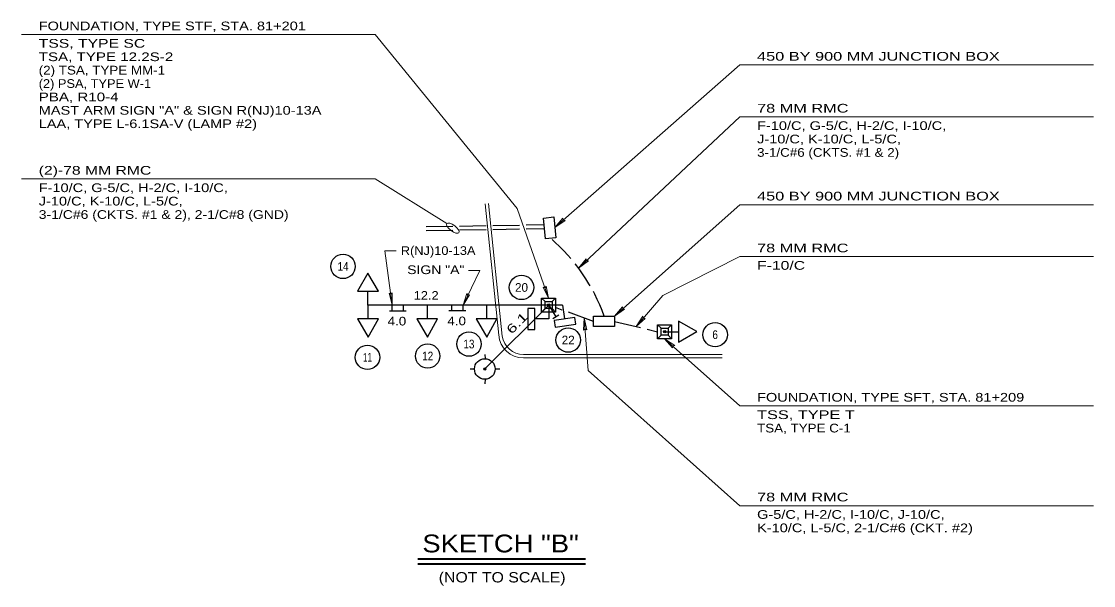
# Model space of a CAD drawing. Extents: x 168203 to 169863, y 223196 to 223870.
# Drawn here: x 168659.4 to 168731.8, y 223261.7 to 223299.8 of the extents above; entities that cross this region are included whole.
import ezdxf
from ezdxf.enums import TextEntityAlignment as Align

# ---------------------------------------------------------------- set-up
doc = ezdxf.new("R2010")
doc.units = 0
doc.header["$LTSCALE"] = 0.3
doc.header["$PDMODE"] = 32
doc.header["$PDSIZE"] = 0.15
doc.linetypes.add('LONG_DASH_SHORT_DASH', pattern=[9.9, 6, -1.2, 1.5, -1.2])
doc.linetypes.add('LONG_DASHED', pattern=[7.5, 6, -1.5])
for name, color, linetype, lineweight in [('1', 7, 'Continuous', 13), ('3', 7, 'Continuous', 25), ('31', 7, 'Continuous', 25), ('5', 7, 'Continuous', 25), ('6', 7, 'LONG_DASHED', 25), ('7', 7, 'Continuous', 25), ('9', 7, 'Continuous', 13)]:
    doc.layers.add(name, color=color, linetype=linetype, lineweight=lineweight)

msp = doc.modelspace()

# ---------------------------------------------------------------- linework, layer by layer
at = {"layer": '1'}
for p, q in [((168691.6329, 223278.6176), (168690.7124, 223287.4748)), ((168691.8712, 223278.5504), (168690.9412, 223287.4985)), ((168706.7124, 223277.0758), (168693.2955, 223277.0758)), ((168706.7124, 223277.3058), (168693.3035, 223277.3058))]:
    msp.add_line(p, q, dxfattribs=at)
for radius, start, end in [(1.6673, 184.13349, 270.00005), (1.4373, 187.706, 270.3211)]:
    msp.add_arc((168693.2955, 223278.7431), radius, start, end, dxfattribs=at)
at = {"layer": '3'}
for p, q in [((168694.5256, 223281.113), (168694.7605, 223280.878)), ((168695.4653, 223281.113), (168695.2304, 223280.878)), ((168694.5256, 223280.1732), (168694.7605, 223280.4082)), ((168695.4653, 223280.1732), (168695.2304, 223280.4082)), ((168702.3536, 223279.313), (168702.5885, 223279.078)), ((168703.2933, 223279.313), (168703.0584, 223279.078)), ((168702.3536, 223278.3732), (168702.5885, 223278.6082)), ((168703.2933, 223278.3732), (168703.0584, 223278.6082))]:
    msp.add_line(p, q, dxfattribs=at)
for points in [[(168694.5256, 223281.113), (168695.4653, 223281.113), (168695.4653, 223280.1732), (168694.5256, 223280.1732)], [(168694.7605, 223280.878), (168695.2304, 223280.878), (168695.2304, 223280.4082), (168694.7605, 223280.4082)], [(168702.3536, 223279.313), (168703.2933, 223279.313), (168703.2933, 223278.3732), (168702.3536, 223278.3732)], [(168702.5885, 223279.078), (168703.0584, 223279.078), (168703.0584, 223278.6082), (168702.5885, 223278.6082)]]:
    msp.add_lwpolyline(points, close=True, dxfattribs=at)
for p in [(168695.0045, 223280.6431), (168702.8325, 223278.8431)]:
    msp.add_point(p, dxfattribs=at)
at = {"layer": '31', "lineweight": 13}
for p, q in [((168683.9455, 223284.304), (168684.7042, 223284.304)), ((168684.4429, 223280.643), (168683.9455, 223284.304)), ((168689.2219, 223280.6438), (168690.3583, 223282.9722)), ((168689.5996, 223282.9722), (168690.3583, 223282.9722))]:
    msp.add_line(p, q, dxfattribs=at)
at = {"layer": '31'}
for p, q in [((168682.8045, 223280.6431), (168682.8045, 223281.5829)), ((168695.0045, 223280.6431), (168682.8045, 223280.6431)), ((168682.8045, 223280.6431), (168682.8045, 223279.7033)), ((168684.4429, 223280.2635), (168684.4429, 223280.643)), ((168685.2019, 223280.2635), (168685.2019, 223280.643)), ((168686.8045, 223280.6431), (168686.8045, 223279.7033)), ((168688.4629, 223280.2643), (168688.4629, 223280.6438)), ((168689.2219, 223280.2643), (168689.2219, 223280.6438)), ((168695.0045, 223280.6431), (168690.6912, 223276.3297)), ((168690.8045, 223280.6431), (168690.8045, 223279.7033)), ((168695.0045, 223280.6431), (168695.0045, 223279.7033)), ((168695.9443, 223280.6431), (168695.0045, 223280.6431)), ((168695.0045, 223280.6431), (168695.4929, 223279.8402)), ((168695.9443, 223280.6431), (168696.0776, 223279.7128)), ((168684.2531, 223280.2635), (168685.3826, 223280.2635)), ((168688.2731, 223280.2643), (168689.4026, 223280.2643)), ((168695.0045, 223279.7033), (168694.0647, 223279.7033)), ((168695.6936, 223279.9623), (168695.2844, 223279.7134)), ((168702.8325, 223278.8431), (168703.7723, 223278.8431))]:
    msp.add_line(p, q, dxfattribs=at)
at = {"layer": '31', "linetype": 'LONG_DASH_SHORT_DASH'}
for points in [[(168682.7864, 223282.8027), (168682.0997, 223281.5829), (168682.8045, 223281.5829), (168683.5093, 223281.5829)], [(168693.5949, 223280.4172), (168693.5949, 223278.9985), (168694.0647, 223278.9985), (168694.0647, 223280.4172)], [(168682.8226, 223278.4835), (168683.5093, 223279.7033), (168682.8045, 223279.7033), (168682.0997, 223279.7033)], [(168686.8226, 223278.4835), (168687.5093, 223279.7033), (168686.8045, 223279.7033), (168686.0997, 223279.7033)], [(168690.8226, 223278.4835), (168691.5093, 223279.7033), (168690.8045, 223279.7033), (168690.0997, 223279.7033)], [(168704.9921, 223278.8612), (168703.7723, 223279.5479), (168703.7723, 223278.8431), (168703.7723, 223278.1383)]]:
    msp.add_lwpolyline(points, close=True, dxfattribs=at)
at = {"layer": '31', "lineweight": 13}
for points in [[(168684.4319, 223281.4623), (168684.4429, 223280.643), (168684.226, 223281.4343), (168684.3444, 223281.3682)], [(168689.6679, 223281.3311), (168689.2219, 223280.6438), (168689.4812, 223281.4222), (168689.5429, 223281.3015)]]:
    msp.add_lwpolyline(points, close=True, dxfattribs=at)
at = {"layer": '31'}
msp.add_lwpolyline([(168695.4376, 223279.1465), (168696.8419, 223279.3477), (168696.7753, 223279.8128), (168695.3709, 223279.6115)], close=True, dxfattribs=at)
for centre in [(168681.124, 223283.2489), (168693.1689, 223281.8297), (168696.3185, 223278.2827), (168706.2354, 223278.644), (168689.6214, 223278.0132), (168682.7725, 223277.116), (168686.8368, 223277.2049)]:
    msp.add_circle(centre, 0.8236, dxfattribs=at)
at = {"layer": '5'}
for points in [[(168694.7902, 223285.1007), (168694.6436, 223286.5118), (168695.3446, 223286.5846), (168695.4912, 223285.1735)], [(168699.4522, 223279.1952), (168698.0335, 223279.1952), (168698.0335, 223279.9), (168699.4522, 223279.9)]]:
    msp.add_lwpolyline(points, close=True, dxfattribs=at)
at = {"layer": '6'}
for p, q in [((168686.7262, 223285.9341), (168694.6895, 223286.0701)), ((168686.7307, 223285.6699), (168694.7169, 223285.8063)), ((168698.0335, 223279.5431), (168695.4653, 223280.4672)), ((168699.4522, 223279.5431), (168702.3536, 223278.8431))]:
    msp.add_line(p, q, dxfattribs=at)
msp.add_arc((168687.1701, 223275.8053), 12.2757, 19.48491, 49.48362, dxfattribs=at)
at = {"layer": '7'}
for p, q in [((168690.7007, 223277.3169), (168690.7071, 223277.0294)), ((168689.9915, 223276.3265), (168689.704, 223276.3201)), ((168691.704, 223276.3265), (168691.3845, 223276.3265)), ((168690.7072, 223275.6365), (168690.7008, 223275.3233))]:
    msp.add_line(p, q, dxfattribs=at)
msp.add_circle((168690.6912, 223276.3297), 0.6965, dxfattribs=at)
msp.add_point((168690.6944, 223276.3265), dxfattribs=at)
at = {"layer": '9'}
for p, q in [((168683.2943, 223298.8853), (168659.4208, 223298.8853)), ((168695.4269, 223285.88), (168707.8988, 223296.8353)), ((168731.7723, 223296.8353), (168707.8988, 223296.8353)), ((168697.0171, 223283.1354), (168707.8988, 223293.3353)), ((168731.7723, 223293.3353), (168707.8988, 223293.3353)), ((168683.2943, 223289.1467), (168659.4208, 223289.1467)), ((168688.1264, 223286.1381), (168683.2943, 223289.1467)), ((168699.4522, 223279.9), (168707.8988, 223287.408)), ((168731.7723, 223287.408), (168707.8988, 223287.408)), ((168731.7723, 223283.908), (168707.8988, 223283.908)), ((168702.828, 223278.3732), (168707.8988, 223273.8389)), ((168731.7723, 223273.8389), (168707.8988, 223273.8389)), ((168731.7723, 223267.1093), (168707.8988, 223267.1093))]:
    msp.add_line(p, q, dxfattribs=at)
at = {"layer": '9', "lineweight": 35}
for p, q in [((168686.1624, 223263.5264), (168697.4782, 223263.5264)), ((168686.1624, 223263.179), (168697.4782, 223263.179))]:
    msp.add_line(p, q, dxfattribs=at)
at = {"layer": '9'}
for points in [[(168695, 223281.113), (168692.8752, 223287.1498), (168683.2943, 223298.8853)], [(168700.8971, 223279.1945), (168702.6968, 223281.289), (168707.8988, 223283.908)], [(168697.3963, 223279.7724), (168697.6767, 223276.232), (168707.8988, 223267.1093)]]:
    msp.add_lwpolyline(points, dxfattribs=at)
for points in [[(168696.1035, 223286.3421), (168695.4269, 223285.88), (168695.9664, 223286.4982), (168695.9768, 223286.363)], [(168697.6785, 223283.6191), (168697.0171, 223283.1354), (168697.5363, 223283.7707), (168697.5511, 223283.6359)], [(168694.8237, 223281.9132), (168695, 223281.113), (168694.6277, 223281.8442), (168694.757, 223281.8034)], [(168700.1261, 223280.366), (168699.4522, 223279.9), (168699.9881, 223280.5213), (168699.9992, 223280.3862)], [(168697.3614, 223278.9538), (168697.3963, 223279.7724), (168697.5686, 223278.9702), (168697.4541, 223279.0428)], [(168701.5025, 223279.7466), (168700.8971, 223279.1945), (168701.3449, 223279.882), (168701.3741, 223279.7496)], [(168703.368, 223277.757), (168702.828, 223278.3732), (168703.5065, 223277.9119), (168703.3736, 223277.8853)]]:
    msp.add_lwpolyline(points, close=True, dxfattribs=at)
msp.add_ellipse((168688.5362, 223285.8283), major_axis=(-0.4098, 0.3098), ratio=0.392166, dxfattribs=at)

# ---------------------------------------------------------------- texts
at = {"layer": '31'}
for s, width, p in [('R(NJ)10-13A', 1.1, (168687.5425, 223284.0217)), ('14', 0.85, (168681.124, 223282.9553)), ('SIGN "A"', 1.2, (168687.3838, 223282.7309)), ('12.2', 1.1, (168686.7348, 223280.9992)), ('4.0', 1.15, (168684.7578, 223279.2636)), ('4.0', 1.15, (168688.7922, 223279.2783)), ('6', 0.85, (168706.2354, 223278.3504)), ('13', 0.85, (168689.6214, 223277.7196)), ('12', 0.85, (168686.8368, 223276.9113)), ('11', 0.7, (168682.7725, 223276.8224))]:
    msp.add_text(s, height=0.5873, dxfattribs=dict(at, width=width)).set_placement(p, align=Align.CENTER)
for s, p in [('20', (168693.169, 223281.5361)), ('22', (168696.3186, 223277.9891))]:
    msp.add_text(s, height=0.5873, dxfattribs=at).set_placement(p, align=Align.CENTER)
at = {"layer": '31', "width": 1.5}
msp.add_text('6.1', height=0.5873, rotation=45.001, dxfattribs=at).set_placement((168693.0752, 223279.2184), align=Align.CENTER)
at = {"layer": '9'}
for s, height, width, p in [('FOUNDATION, TYPE STF, STA. 81+201    ', 0.5873, 1.25, (168660.5865, 223299.1745)), ('TSS, TYPE SC                         ', 0.5873, 1.35, (168660.5865, 223297.9998)), ('450 BY 900 MM JUNCTION BOX           ', 0.5873, 1.4, (168709.0645, 223297.1245)), ('TSA, TYPE 12.2S-2                    ', 0.5873, 1.3, (168660.5865, 223297.0961)), ('(2) TSA, TYPE MM-1                   ', 0.5873, 1.15, (168660.5865, 223296.1925)), ('(2) PSA, TYPE W-1                    ', 0.5873, 1.1, (168660.5865, 223295.2889)), ('PBA, R10-4                           ', 0.5873, 1.3, (168660.5865, 223294.3853)), ('MAST ARM SIGN "A" & SIGN R(NJ)10-13A ', 0.5873, 1.25, (168660.5865, 223293.4817)), ('78 MM RMC                            ', 0.5873, 1.4, (168709.0645, 223293.6245)), ('LAA, TYPE L-6.1SA-V (LAMP #2)   ', 0.5873, 1.25, (168660.5865, 223292.5781)), ('F-10/C, G-5/C, H-2/C, I-10/C,', 0.5873, 1.25, (168709.0645, 223292.4498)), ('J-10/C, K-10/C, L-5/C,        ', 0.5873, 1.25, (168709.0645, 223291.5461)), ('3-1/C#6 (CKTS. #1 & 2)     ', 0.5873, 1.15, (168709.0645, 223290.6425)), ('(2)-78 MM RMC                          ', 0.5873, 1.35, (168660.5865, 223289.4359)), ('F-10/C, G-5/C, H-2/C, I-10/C,', 0.5873, 1.25, (168660.5865, 223288.2612)), ('J-10/C, K-10/C, L-5/C,        ', 0.5873, 1.25, (168660.5865, 223287.3575)), ('450 BY 900 MM JUNCTION BOX           ', 0.5873, 1.4, (168709.0645, 223287.6972)), ('3-1/C#6 (CKTS. #1 & 2), 2-1/C#8 (GND) ', 0.5873, 1.2, (168660.5865, 223286.4539)), ('78 MM RMC                            ', 0.5873, 1.4, (168709.0645, 223284.1972)), ('F-10/C                     ', 0.5873, 1.35, (168709.0645, 223283.0225)), ('FOUNDATION, TYPE SFT, STA. 81+209    ', 0.5873, 1.25, (168709.0645, 223274.1281)), ('TSS, TYPE T                          ', 0.5873, 1.4, (168709.0645, 223272.9534)), ('TSA, TYPE C-1                        ', 0.5873, 1.15, (168709.0645, 223272.0497)), ('78 MM RMC                            ', 0.5873, 1.4, (168709.0645, 223267.3985)), ('G-5/C, H-2/C, I-10/C, J-10/C, ', 0.5873, 1.25, (168709.0645, 223266.2238)), ('K-10/C, L-5/C, 2-1/C#6 (CKT. #2) ', 0.5873, 1.25, (168709.0645, 223265.3201)), ('(NOT TO SCALE)', 0.6958, 1.15, (168687.5805, 223261.9335))]:
    msp.add_text(s, height=height, dxfattribs=dict(at, width=width)).set_placement(p)
at = {"layer": '9', "width": 1.15}
msp.add_text('SKETCH "B"', height=1.202, dxfattribs=at).set_placement((168691.7536, 223263.9601), align=Align.CENTER)

doc.saveas('drawing.dxf')
